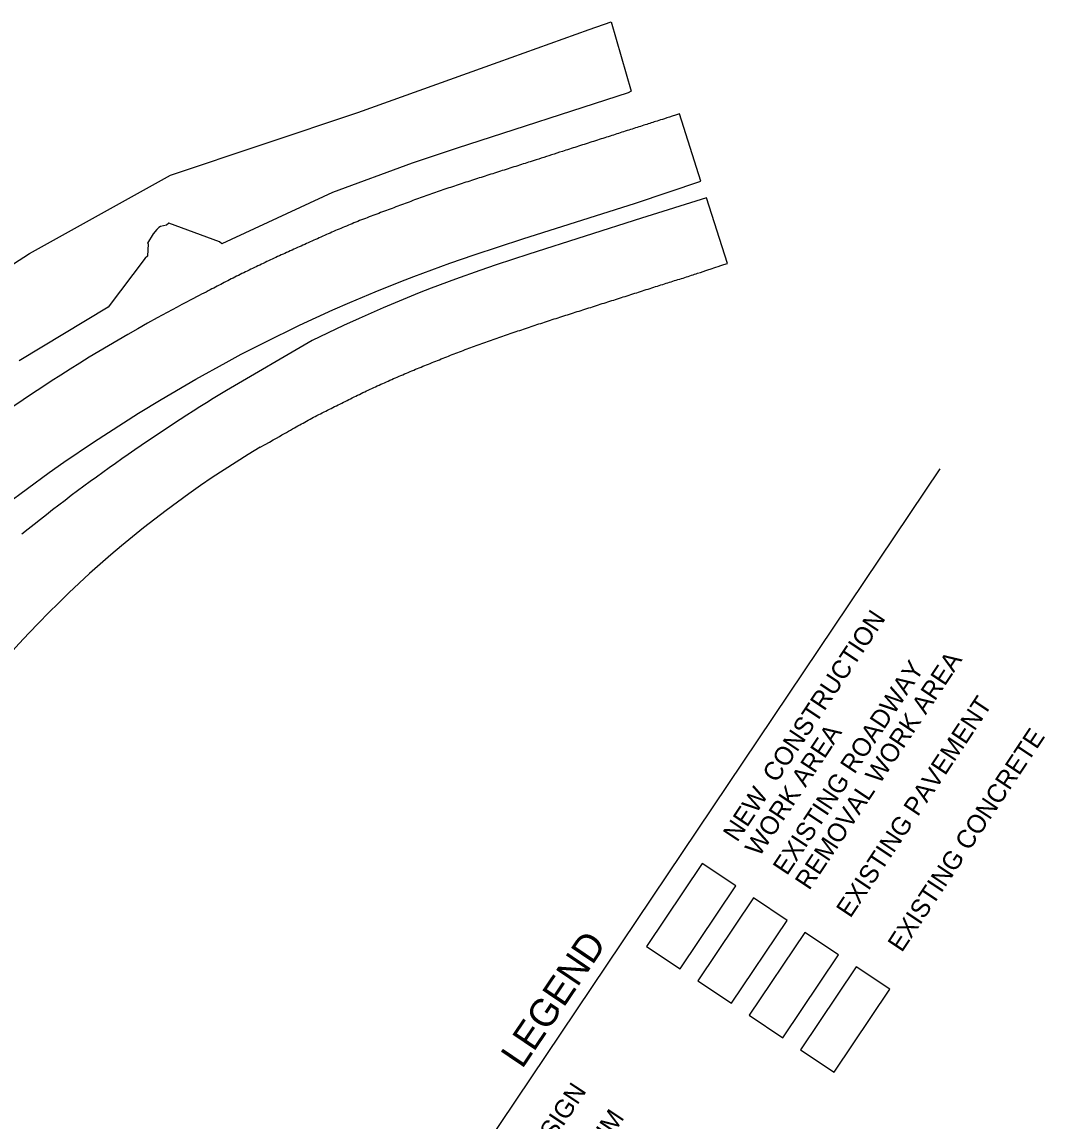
# Model space of a CAD drawing. Extents: x 1795987 to 1799700, y 243690 to 251545.
# Drawn here: x 1798428.4 to 1798861.5, y 250514.1 to 250979.5 of the extents above; entities that cross this region are included whole.
import ezdxf

# ---------------------------------------------------------------- set-up
doc = ezdxf.new("R2010")
doc.units = 0
doc.layers.add('LEGEND', color=7, linetype='Continuous')
doc.layers.add('Level 62', color=7, linetype='Continuous')

msp = doc.modelspace()

# ---------------------------------------------------------------- linework, layer by layer
at = {"layer": 'LEGEND'}
msp.add_line((1798551.69, 250395.05), (1798817.07, 250790.3), dxfattribs=at)
for points in [[(1798706.99, 250578.57), (1798730.56, 250613.67), (1798716.38, 250623.19), (1798692.82, 250588.09)], [(1798728.71, 250563.99), (1798752.28, 250599.09), (1798738.11, 250608.6), (1798714.54, 250573.51)], [(1798750.44, 250549.41), (1798774, 250584.5), (1798759.83, 250594.02), (1798736.26, 250558.92)], [(1798772.16, 250534.82), (1798795.72, 250569.92), (1798781.55, 250579.43), (1798757.99, 250544.34)]]:
    msp.add_lwpolyline(points, close=True, dxfattribs=at)
at = {"layer": 'Level 62'}
for p, q in [((1798668.45, 250976.22), (1798677.83, 250979.45)), ((1798668.45, 250976.22), (1798677.83, 250979.45)), ((1798677.83, 250979.45), (1798686.34, 250950.23)), ((1798677.83, 250979.45), (1798686.34, 250950.23)), ((1798630, 250962.47), (1798668.45, 250976.22)), ((1798630, 250962.47), (1798668.45, 250976.22)), ((1798570.52, 250941.2), (1798630, 250962.47)), ((1798570.52, 250941.2), (1798630, 250962.47)), ((1798491.32, 250914.63), (1798570.52, 250941.2)), ((1798491.32, 250914.63), (1798570.52, 250941.2)), ((1798612.69, 250926), (1798593.64, 250919.71)), ((1798612.69, 250926), (1798593.64, 250919.71)), ((1798593.64, 250919.71), (1798559.85, 250907.31)), ((1798593.64, 250919.71), (1798559.85, 250907.31)), ((1798431.57, 250881.49), (1798491.32, 250914.63)), ((1798431.57, 250881.49), (1798491.32, 250914.63)), ((1798559.85, 250907.31), (1798513, 250885.53)), ((1798559.85, 250907.31), (1798513, 250885.53)), ((1798489.61, 250893.48), (1798487.03, 250892.83)), ((1798489.61, 250893.48), (1798487.03, 250892.83)), ((1798490.6, 250894.25), (1798489.61, 250893.48)), ((1798490.6, 250894.25), (1798489.61, 250893.48)), ((1798512, 250886.32), (1798490.6, 250894.25)), ((1798512, 250886.32), (1798490.6, 250894.25)), ((1798513, 250885.53), (1798512, 250886.32)), ((1798513, 250885.53), (1798512, 250886.32)), ((1798399.82, 250860.78), (1798431.57, 250881.49)), ((1798399.82, 250860.78), (1798431.57, 250881.49)), ((1798480.51, 250879.39), (1798464.83, 250858.78)), ((1798480.51, 250879.39), (1798464.83, 250858.78)), ((1798481.52, 250880.29), (1798480.51, 250879.39)), ((1798481.52, 250880.29), (1798480.51, 250879.39)), ((1798464.83, 250858.78), (1798427.17, 250835.94)), ((1798464.83, 250858.78), (1798427.17, 250835.94))]:
    msp.add_line(p, q, dxfattribs=at)
for points in [[(1798686.34, 250950.23), (1798685.01, 250949.46), (1798612.69, 250926)], [(1798686.34, 250950.23), (1798685.01, 250949.46), (1798612.69, 250926)], [(1798688.08, 250902.78), (1798715.83, 250911.99), (1798706.71, 250940.52)], [(1798727, 250877.2), (1798718.12, 250905.04), (1798690.64, 250896.35), (1798643.02, 250881.17), (1798629.12, 250876.63), (1798622.21, 250874.27), (1798611.89, 250870.6), (1798601.64, 250866.75), (1798596.54, 250864.76), (1798591.43, 250862.7), (1798581.28, 250858.44), (1798571.21, 250853.98), (1798564.54, 250850.91), (1798551.3, 250844.54), (1798514.99, 250823.48)], [(1798421.6, 250775.14), (1798430.71, 250781.98), (1798439.94, 250788.67), (1798446.15, 250793.04), (1798458.71, 250801.58), (1798471.32, 250809.8), (1798477.69, 250813.81), (1798487.33, 250819.69), (1798501.95, 250828.23), (1798514.78, 250835.33), (1798521.26, 250838.77), (1798531.03, 250843.81), (1798545.85, 250851.06), (1798560.03, 250857.58), (1798567.18, 250860.72), (1798577.96, 250865.27), (1798588.83, 250869.62), (1798594.28, 250871.72), (1798609.55, 250877.31), (1798619.79, 250880.85), (1798640.4, 250887.61), (1798688.08, 250902.78)], [(1798485.52, 250891.59), (1798483.88, 250889.72), (1798481.58, 250885.86)], [(1798485.52, 250891.59), (1798483.88, 250889.72), (1798481.58, 250885.86)], [(1798487.03, 250892.83), (1798486.29, 250892.47), (1798485.52, 250891.59)], [(1798487.03, 250892.83), (1798486.29, 250892.47), (1798485.52, 250891.59)], [(1798481.58, 250885.86), (1798481.89, 250885.49), (1798481.52, 250880.29)], [(1798481.58, 250885.86), (1798481.89, 250885.49), (1798481.52, 250880.29)], [(1798736.26, 250558.92), (1798750.44, 250549.41), (1798774, 250584.5), (1798759.83, 250594.02), (1798736.26, 250558.92)]]:
    msp.add_lwpolyline(points, dxfattribs=at)
for centre, radius, start, end in [((1798847.29, 250198.62), 748.7, 118.15094, 129.80104), ((1798929.58, 250141.63), 798, 121.30087, 128.9046), ((1798765.83, 250404.81), 460.1, 120.9411, 144.8621)]:
    msp.add_arc(centre, radius, start, end, dxfattribs=at)
for points in [[(1798706.71, 250940.52), (1798702.17, 250939.08), (1798697.63, 250937.63), (1798693.09, 250936.18), (1798687.38, 250934.36), (1798681.67, 250932.52), (1798675.95, 250930.68), (1798669.6, 250928.65), (1798663.25, 250926.61), (1798656.9, 250924.57), (1798652.58, 250923.18), (1798648.25, 250921.79), (1798643.93, 250920.4), (1798637.43, 250918.31), (1798630.92, 250916.26), (1798624.42, 250914.18), (1798617.93, 250912.1), (1798611.45, 250909.99), (1798605, 250907.8), (1798598.59, 250905.61), (1798592.26, 250903.21), (1798585.91, 250900.84), (1798579.43, 250898.42), (1798572.94, 250896.02), (1798566.54, 250893.37), (1798560.32, 250890.81), (1798554.21, 250888.04), (1798548.08, 250885.29), (1798541.97, 250882.53), (1798535.85, 250879.79), (1798529.8, 250876.91), (1798523.76, 250874.03), (1798517.76, 250871.07), (1798511.83, 250867.99), (1798505.91, 250864.91), (1798499.98, 250861.83), (1798494.06, 250858.75)], [(1798529.27, 250799.44), (1798535.08, 250802.71), (1798540.89, 250805.98), (1798546.7, 250809.25), (1798552.52, 250812.53), (1798558.52, 250815.47), (1798564.5, 250818.45), (1798570.5, 250821.44), (1798576.52, 250824.34), (1798582.64, 250827.07), (1798588.79, 250829.82), (1798594.99, 250832.41), (1798601.24, 250834.92), (1798607.44, 250837.42), (1798613.65, 250839.87), (1798619.93, 250842.16), (1798626.31, 250844.49), (1798632.7, 250846.76), (1798639.15, 250848.9), (1798645.61, 250851.05), (1798652.08, 250853.2), (1798658.57, 250855.27), (1798665.07, 250857.34), (1798671.58, 250859.42), (1798678.08, 250861.49), (1798684.56, 250863.55), (1798691.04, 250865.61), (1798697.52, 250867.68), (1798703.23, 250869.5), (1798708.97, 250871.26), (1798714.67, 250873.14), (1798718.78, 250874.49), (1798722.89, 250875.85), (1798727, 250877.2)]]:
    msp.add_open_spline(points, degree=3, dxfattribs=at)

# ---------------------------------------------------------------- texts
at = {"layer": 'LEGEND'}
for s, height, rotation, p in [('NEW  CONSTRUCTION', 7.7999, 56.4352, (1798731.16, 250631.88)), ('EXISTING ROADWAY', 7.7999, 56.4352, (1798752.25, 250617.72)), ('REMOVAL WORK AREA', 7.7999, 56.4352, (1798761.62, 250611.5)), ('EXISTING PAVEMENT', 7.7999, 56.4352, (1798779.07, 250599.73)), ('WORK AREA', 7.8, 56.4352, (1798740.52, 250625.66)), ('EXISTING CONCRETE', 7.7999, 56.4352, (1798800.83, 250585.21)), ('LEGEND', 11.7, 55.9561, (1798640.14, 250535.91)), ('TRAFFIC CONTROL SIGN', 7.7999, 56.4352, (1798597.78, 250421.64)), ('CHANNELIZATION DRUM', 7.7999, 56.4352, (1798614.45, 250411.34))]:
    msp.add_text(s, height=height, rotation=rotation, dxfattribs=at).set_placement(p)

doc.saveas('drawing.dxf')
